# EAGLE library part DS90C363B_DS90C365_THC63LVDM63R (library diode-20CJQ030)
National Smeiconductors DS90CF363B +3.3V Programmable LVDS Transmitter 18-Bit Flat Panel Display (FPD) Link -65 MHz General Description: The DS90CF363B transmitter converts 21 bits of CMOS/TTL data into three LVDS (Low Voltage Differential Signaling) data streams. A phase-locked transmit clock is transmitted in parallel with the data streams over a fourth LVDS link. Every cycle of the transmit clock 21 bits of input data are sampled and transmitted. At a transmit clock frequency of 65 MHz, 18 bits of RGB data and 3 bits of LCD timing and control data (FPLINE, FPFRAME, DRDY) are transmitted at a rate of 455 Mbps per LVDS data channel. Using a 65 MHz clock, the data throughput is 170 Mbytes/sec. The DS90CF363B is fixed as a Falling edge strobe transmitter and will interoperate with a Falling edge strobe Receiver (DS90CF366) without any translation logic. This chipset is an ideal means to solve EMI and cable size problems associated with wide, high speed TTL interfaces. Features: No special start-up sequence required between clock/data and /PD pins. Input signal (clock and data) can be applied either before or after the device is powered. Support Spread Spectrum Clocking up to 100KHz frequency modulation & deviations of ±2.5% center spread or 5% down spread. "Input Clock Detection" feature will pull all LVDS pairs to logic low when input clock is missing and when /PD pin is logic high. 18 to 68 MHz shift clock support Best-in-Class Set & Hold Times on TxINPUTs Tx power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
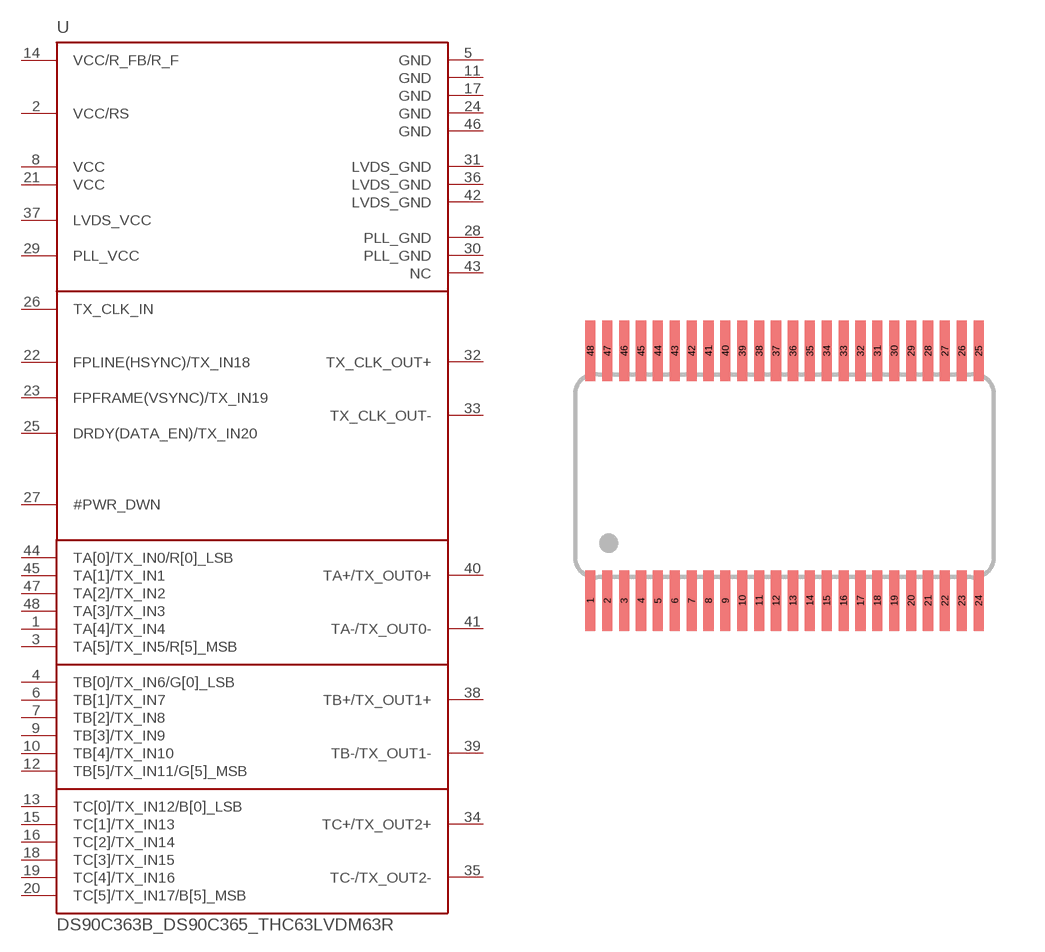
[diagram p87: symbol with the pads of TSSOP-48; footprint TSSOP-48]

Designator prefix U

## DS90C363B_DS90C365_THC63LVDM63R  [TSSOP-48]
1  TA[4]/TX_IN4  in
2  VCC/RS  pwr
3  TA[5]/TX_IN5/R[5]_MSB  in
4  TB[0]/TX_IN6/G[0]_LSB  in
5  GND  pwr
6  TB[1]/TX_IN7  in
7  TB[2]/TX_IN8  in
8  VCC  pwr
9  TB[3]/TX_IN9  in
10  TB[4]/TX_IN10  in
11  GND  pwr
12  TB[5]/TX_IN11/G[5]_MSB  in
13  TC[0]/TX_IN12/B[0]_LSB  in
14  VCC/R_FB/R_F  pwr
15  TC[1]/TX_IN13  in
16  TC[2]/TX_IN14  in
17  GND  pwr
18  TC[3]/TX_IN15  in
19  TC[4]/TX_IN16  in
20  TC[5]/TX_IN17/B[5]_MSB  in
21  VCC  pwr
22  FPLINE(HSYNC)/TX_IN18
23  FPFRAME(VSYNC)/TX_IN19
24  GND  pwr
25  DRDY(DATA_EN)/TX_IN20
26  TX_CLK_IN  in
27  #PWR_DWN
28  PLL_GND  pwr
29  PLL_VCC  pwr
30  PLL_GND  pwr
31  LVDS_GND  pwr
32  TX_CLK_OUT+  out
33  TX_CLK_OUT-  out
34  TC+/TX_OUT2+  out
35  TC-/TX_OUT2-  out
36  LVDS_GND  pwr
37  LVDS_VCC  pwr
38  TB+/TX_OUT1+  out
39  TB-/TX_OUT1-  out
40  TA+/TX_OUT0+  out
41  TA-/TX_OUT0-  out
42  LVDS_GND  pwr
43  NC  nc
44  TA[0]/TX_IN0/R[0]_LSB  in
45  TA[1]/TX_IN1  in
46  GND  pwr
47  TA[2]/TX_IN2  in
48  TA[3]/TX_IN3  in

## Footprint TSSOP-48 (pad centres in mm)
smd 0.3 x 1.8: 1 -5.75,-3.7; 2 -5.25,-3.7; 3 -4.75,-3.7; 4 -4.25,-3.7; 5 -3.75,-3.7; 6 -3.25,-3.7; 7 -2.75,-3.7; 8 -2.25,-3.7; 9 -1.75,-3.7; 10 -1.25,-3.7; 11 -0.75,-3.7; 12 -0.25,-3.7; 13 0.25,-3.7; 14 0.75,-3.7; 15 1.25,-3.7; 16 1.75,-3.7; 17 2.25,-3.7; 18 2.75,-3.7; 19 3.25,-3.7; 20 3.75,-3.7; 21 4.25,-3.7; 22 4.75,-3.7; 23 5.25,-3.7; 24 5.75,-3.7; 25 5.75,3.7; 26 5.25,3.7; 27 4.75,3.7; 28 4.25,3.7; 29 3.75,3.7; 30 3.25,3.7; 31 2.75,3.7; 32 2.25,3.7; 33 1.75,3.7; 34 1.25,3.7; 35 0.75,3.7; 36 0.25,3.7; 37 -0.25,3.7; 38 -0.75,3.7; 39 -1.25,3.7; 40 -1.75,3.7; 41 -2.25,3.7; 42 -2.75,3.7; 43 -3.25,3.7; 44 -3.75,3.7; 45 -4.25,3.7; 46 -4.75,3.7; 47 -5.25,3.7; 48 -5.75,3.7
